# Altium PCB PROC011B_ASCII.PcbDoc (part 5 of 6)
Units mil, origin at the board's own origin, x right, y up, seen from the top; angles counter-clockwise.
Board outline 3304 x 2569 mil, 6 copper layers (TOP, L2-GND1, L3-GND/SIG, L4-GND/SIG, L5-GND2, BOTTOM), stack 55.77 mil thick; 376 components, 289 nets, 1284 pads, 1755 vias.
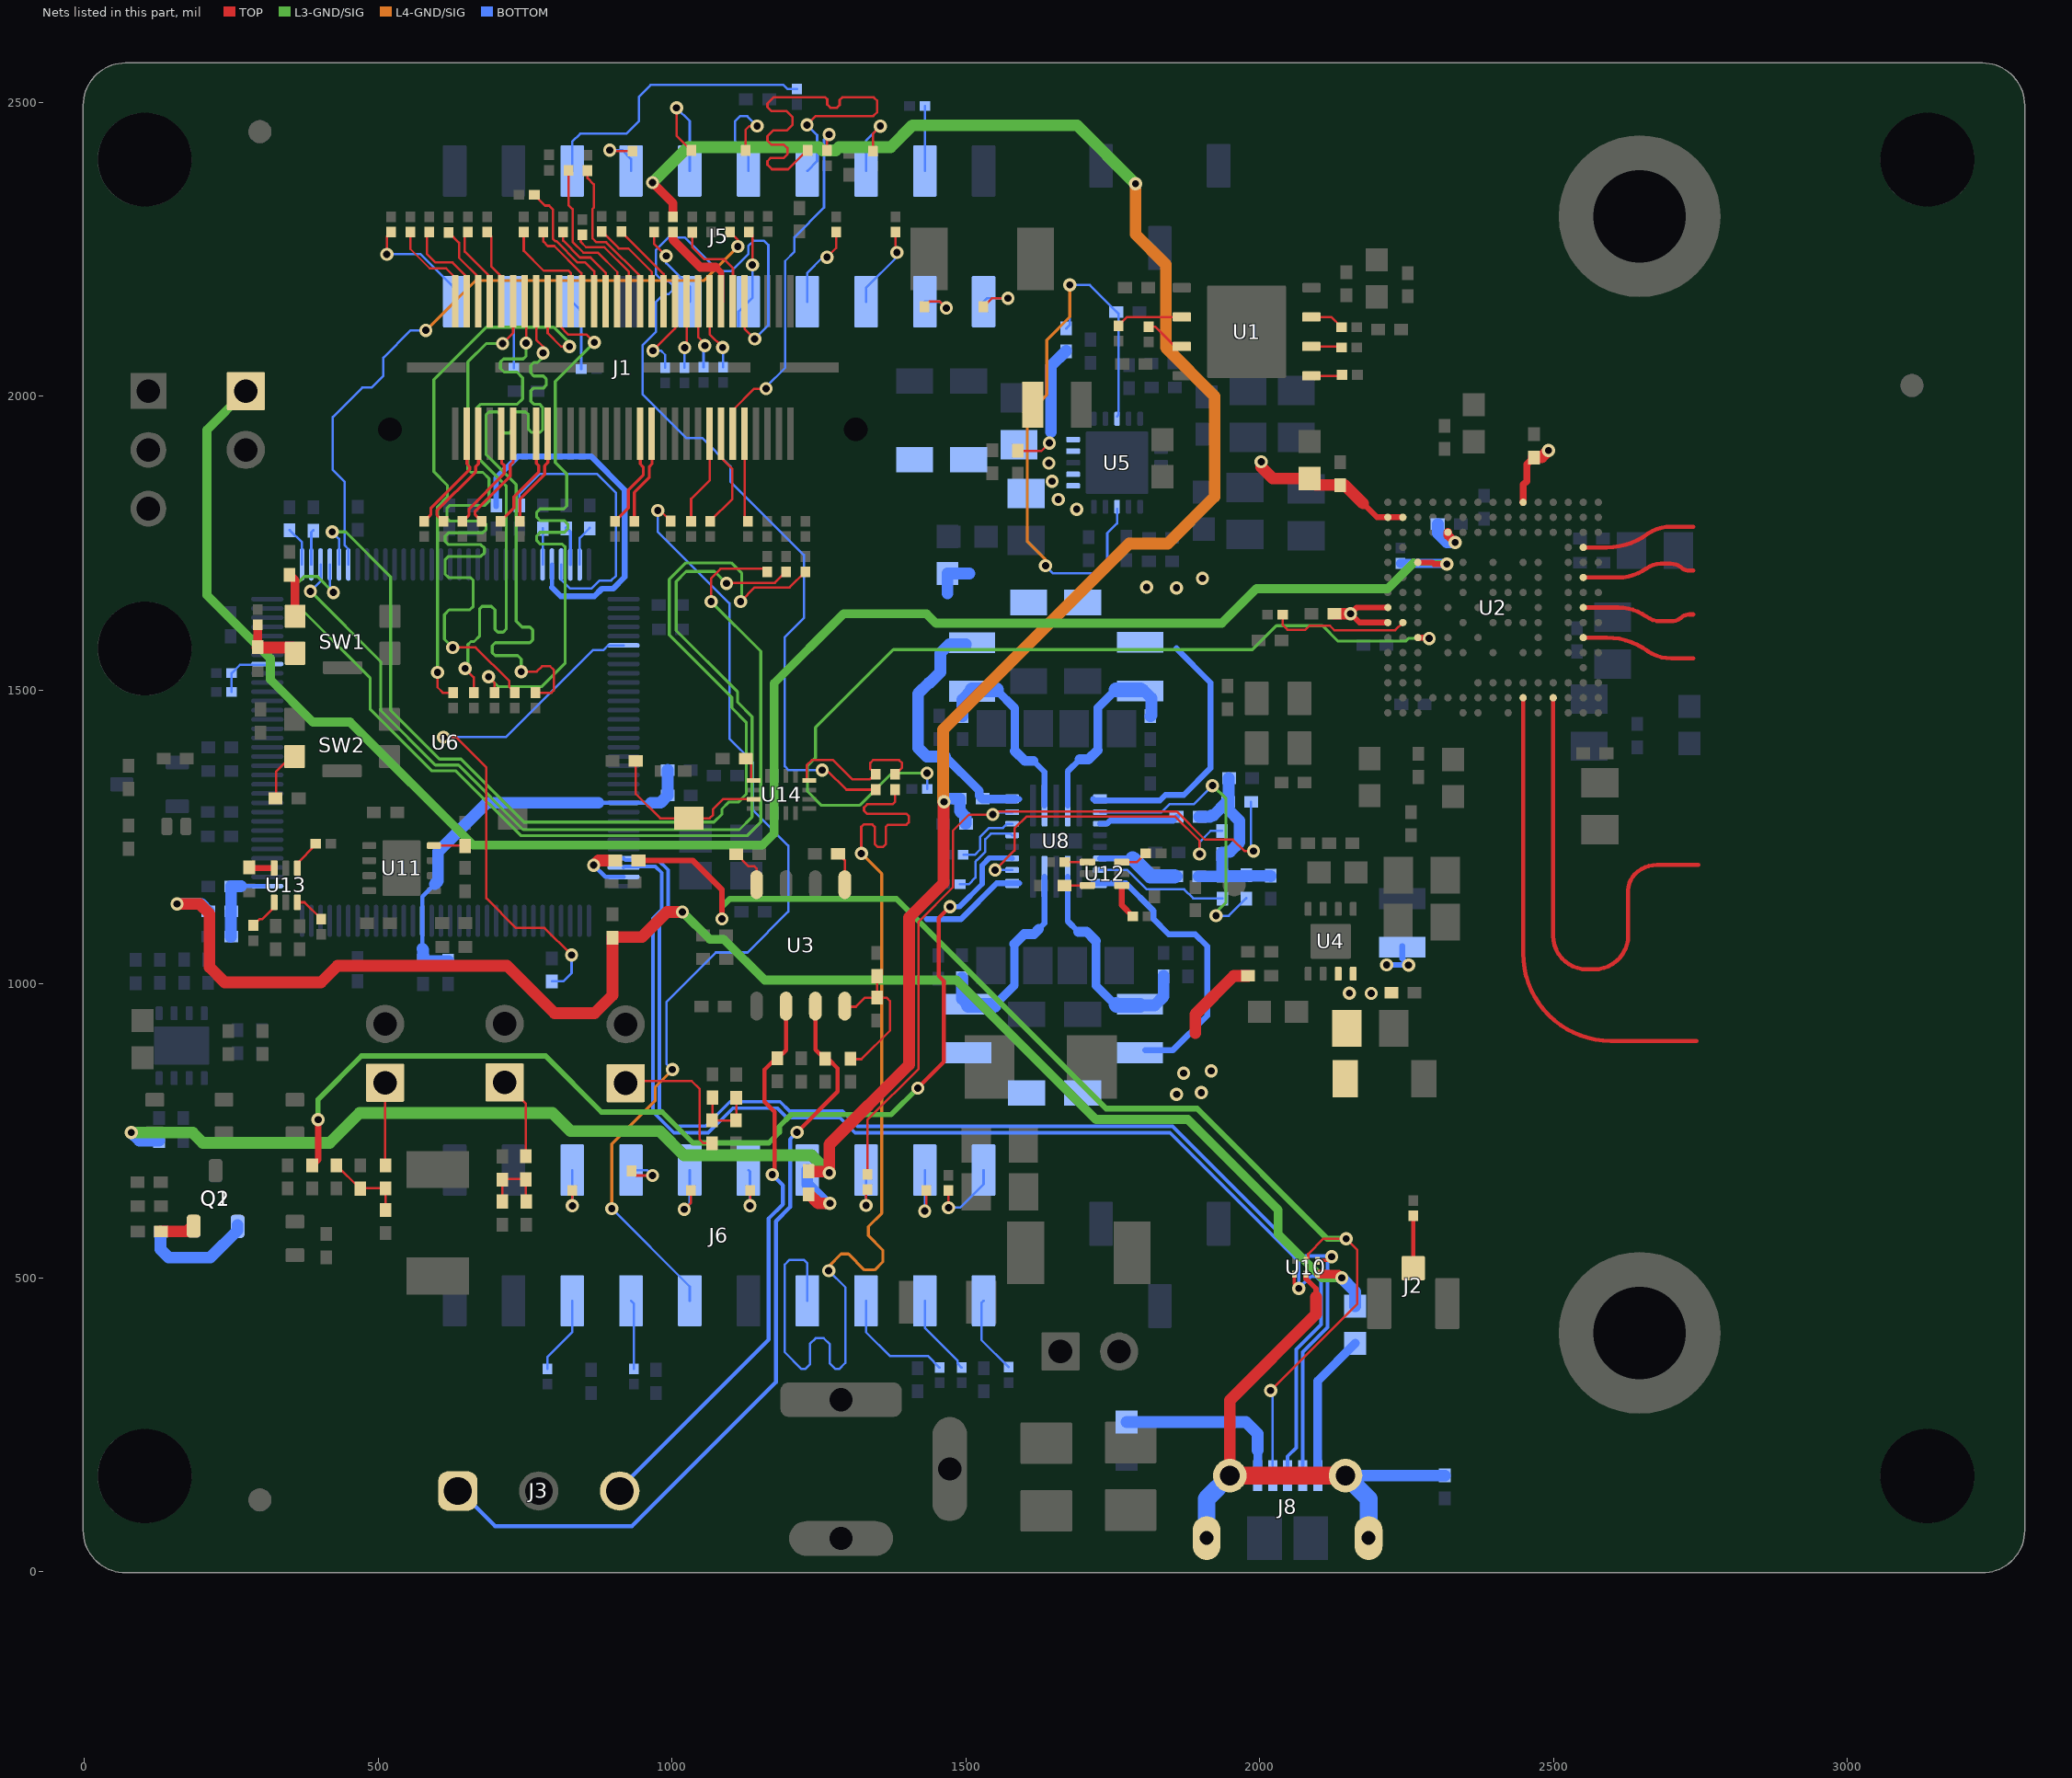
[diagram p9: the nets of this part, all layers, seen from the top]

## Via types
v1: diameter 22.4, hole 12.2, TOP to BOTTOM, tented both sides, 1046 vias
v2: diameter 15.74, hole 5.9, TOP to L2-GND1, tented both sides, 700 vias
v3: diameter 19.68, hole 7.87, TOP to BOTTOM, tented both sides, 9 vias

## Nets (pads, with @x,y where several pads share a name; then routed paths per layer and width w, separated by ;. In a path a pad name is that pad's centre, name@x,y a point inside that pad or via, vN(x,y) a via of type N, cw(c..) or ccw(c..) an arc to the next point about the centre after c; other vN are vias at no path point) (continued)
NetJ1_9: J1.9 R75.2 | length 1734.2
  TOP w4: J1.9@1123.49,2161.75 1123.49,2161.56 1123.49,2114.76 v1(1140.75,2097.5) ; v1(1255.52,1363.62) 1263.64,1363.62 1296.76,1330.51 R75.2@1346.75,1330.51
  BOTTOM w4: v1(1140.75,2097.5) 1164.05,2120.8 1164.05,2257.15 1156.46,2264.74 1139.39,2264.74 1129.85,2255.2 1129.85,2241.53 1100.94,2212.62 1079.22,2212.62 1022.14,2269.7 993.68,2269.7 972.45,2248.47 972.45,2207.63 984.38,2195.7 994.44,2195.7 1001.13,2189.01 1001.13,2180.38 994.43,2173.68 985.82,2173.68 972.45,2160.31 972.45,2109.37 949.76,2086.68 949.76,2003.46 1024.13,1929.09 1051.28,1929.09 1099.45,1880.92 1099.45,1854.8 1224.65,1729.6 1224.65,1622.75 1192.11,1590.21 1192.11,1370.14 1198.63,1363.62 v1(1255.52,1363.62)
NetJ1_10: J1.10 R64.1 | length 151
  TOP w4: J1.10@1123.49,1935.77 1123.49,1793.08 R64.1@1129.36,1787.21
NetJ1_11: J1.11 R28.2 | length 165.5
  TOP w4: R28.2@1034.25,2278.91 1034.25,2254 1054.75,2233.5 1088.16,2233.5 1103.81,2217.85 J1.11@1103.81,2161.75
NetJ1_12: J1.12 R7.1 | length 617.8
  TOP w4: J1.12@1103.4,1935.96 1103.4,1976.36 1139.88,2012.84 v1(1160.01,2012.84) ; J1.12@1103.81,1935.77 J1.12@1103.81,1935.96 ; R7.1@1264,2418.21 1264,2442.11 v1(1267.28,2445.39)
  BOTTOM w4: v1(1160.01,2012.84) 1160.01,2015.76 1192.62,2048.37 1192.62,2230.05 1208.45,2245.87 1208.45,2270.6 1258.75,2320.9 1258.75,2436.86 v1(1267.28,2445.39)
NetJ1_13: J1.13 R27.2 | length 167
  TOP w10: 1074.75,2219.5 1084.12,2210.13 J1.13@1084.12,2161.75
  TOP w15: R27.2@1001.55,2279.01 1001.55,2266.2 1048.25,2219.5 1074.75,2219.5
NetJ1_14: J1.14 R63.1 | length 172
  TOP w4: R63.1@1064.86,1787.21 1102.75,1825.1 1102.75,1875.89 1084.12,1894.52 J1.14@1084.12,1935.77
NetJ1_15: J1.15 R54.2 | length 121.7
  TOP w4: J1.15@1064.03,2161.56 1064.03,2105.22 v1(1086.25,2083) ; J1.15@1064.44,2161.56 J1.15@1064.44,2161.75
  BOTTOM w4: v1(1086.25,2083) 1086.75,2082.5 R54.2@1086.75,2049.49
NetJ1_16: J1.16 R62.1 | length 161.7
  TOP w4: R62.1@1032.6,1787.21 1032.6,1825.35 1064.44,1857.19 J1.16@1064.44,1935.77
NetJ1_17: J1.17 R55.2 | length 117.9
  TOP w4: J1.17@1044.75,2161.75 1044.75,2161.56 1044.75,2100.5 1055.87,2089.38 v1(1055.87,2086.09)
  BOTTOM w4: R55.2@1053.75,2049.29 1053.75,2075.5 1055.87,2077.62 v1(1055.87,2086.09)
NetJ1_19: J1.19 R56.2 | length 114.5
  TOP w4: v1(1021.75,2082.5) 1025.07,2085.82 1025.07,2161.56 J1.19@1025.07,2161.75
  BOTTOM w4: R56.2@1021.25,2048.79 1021.25,2082 v1(1021.75,2082.5)
NetJ1_21: J1.21 R57.2 | length 145
  TOP w4: v1(967.75,2077.5) 1005.38,2115.13 1005.38,2161.56 J1.21@1005.38,2161.75
  BOTTOM w4: v1(967.75,2077.5) 981.25,2077.5 988.35,2070.4 R57.2@988.35,2048.79
NetJ1_23: J1.23 R179.2 | length 148.1
  TOP w4: R179.2@913.75,2280.01 985.7,2208.06 J1.23@985.7,2161.75
NetJ1_25: J1.25 R180.2 | length 163.6
  TOP w4: R180.2@880.45,2280.21 881.04,2280.21 909.75,2251.5 925.75,2251.5 966.01,2211.24 J1.25@966.01,2161.75
NetJ1_26: J1.26 R59.1 | length 161.1
  TOP w5.2: R59.1@935.8,1787.21 935.8,1836.05 961.27,1861.52 961.27,1879.81 966.01,1884.55 J1.26@966.01,1935.77
NetJ1_27: J1.27 R181.2 | length 270.8
  TOP w4: R181.2@856.25,2383.81 856.25,2371 866.75,2360.5 866.75,2320.5 864.75,2318.5 864.75,2268.5 871.25,2262 887.85,2262 946.33,2203.52 J1.27@946.33,2161.75
NetJ1_28: J1.28 R58.1 | length 170.3
  TOP w5.2: R58.1@903.3,1787.21 925.6,1809.51 925.6,1840.28 951.07,1865.75 951.07,1879.81 946.33,1884.55 J1.28@946.33,1935.77
NetJ1_29: J1.29 R182.2 | length 166.1
  TOP w4: R182.2@847.75,2274.51 844.75,2271.51 844.75,2262.51 853.76,2253.5 884.75,2253.5 926.64,2211.61 J1.29@926.64,2161.75
NetJ1_31: J1.31 R183.2 | length 271.6
  TOP w4: R183.2@823.75,2384.21 823.75,2325.1 830.75,2318.1 830.75,2262.5 849.05,2244.2 874.05,2244.2 906.96,2211.29 J1.31@906.96,2161.75
NetJ1_33: J1.33 R184.2 | length 158.3
  TOP w4: R184.2@814.75,2279.51 814.75,2264.51 843.36,2235.9 861.35,2235.9 887.27,2209.98 J1.33@887.27,2161.75
NetJ1_35: J1.35 R185.2 | length 235.8
  TOP w4: R185.2@765.74,2342.5 783.94,2324.3 790.95,2324.3 797.35,2317.9 797.35,2267.9 801.75,2263.5 803.75,2263.5 839.65,2227.6 852.55,2227.6 867.59,2212.56 J1.35@867.59,2161.75
NetJ1_37: J1.37 R186.2 | length 151.9
  TOP w4: R186.2@781.05,2279.51 781.05,2263.2 788.75,2255.5 799.75,2255.5 845.75,2209.5 845.75,2163.9 847.79,2161.86 J1.37@847.9,2161.75
NetJ1_39: J1.39 R187.2 | length 176
  TOP w4: R187.2@747.75,2279.51 747.75,2247.5 781.75,2213.5 824.22,2213.5 828.22,2209.5 J1.39@828.22,2161.75
NetJ1_41: J1.41 R188.2 | length 1058.5
  TOP w4: v1(687.75,1522.6) 697.75,1512.6 R188.2@697.75,1495.59 ; J1.41@808.53,2161.75 808.53,2161.56 808.53,2119.92 823.95,2104.5 854.75,2104.5 v1(867.75,2091.5)
  L3-GND/SIG w5: v1(687.75,1522.6) 704.77,1505.58 777.83,1505.58 818.25,1546 818.25,1743.34 813.25,1748.34 775.61,1748.34 769.75,1754.2 769.75,1762.48 775.61,1768.34 816.89,1768.34 822.75,1774.2 822.75,1782.48 816.89,1788.34 775.61,1788.34 769.75,1794.2 769.75,1802.48 775.61,1808.34 815.85,1808.34 820.85,1813.34 820.85,1867.9 801.35,1887.4 801.35,2025.1 v1(867.75,2091.5)
NetJ1_43: J1.43 R189.2 | length 956.7
  TOP w4: v1(601.05,1530.2) 601.05,1504.6 610.06,1495.59 R189.2@627.75,1495.59 ; J1.43@788.44,2161.56 788.44,2107.29 811.23,2084.5 v1(825.75,2084.5) ; J1.43@788.85,2161.56 J1.43@788.85,2161.75
  L3-GND/SIG w5: v1(601.05,1530.2) 601.05,1811.8 617.75,1828.5 617.75,1848.5 594.75,1871.5 594.75,2028 684.25,2117.5 798.75,2117.5 825.75,2090.5 v1(825.75,2084.5)
NetJ1_44: J1.44 R53.1 | length 168.4
  TOP w5.2: R53.1@741,1787.21 741,1824.74 783.25,1866.99 783.25,1881.49 788.85,1887.09 J1.44@788.85,1935.77
NetJ1_45: J1.45 R190.2 | length 1191.9
  TOP w4: v1(743.45,1531.4) 769.65,1531.4 778.75,1540.5 792.75,1540.5 798.75,1534.5 798.75,1499.59 794.75,1495.59 R190.2@767.75,1495.59 ; J1.45@769.16,2161.75 769.16,2161.56 769.16,2096.09 780.75,2084.5 v1(780.75,2073.5) v1@780.75,2072.5
  L3-GND/SIG w5: v1(743.45,1531.4) 743.45,1552.7 737.55,1558.6 699.29,1558.6 694.29,1563.6 694.29,1575.5 699.29,1580.5 758.15,1580.5 763.15,1585.5 763.15,1602.2 758.15,1607.2 744.75,1607.2 734.75,1617.2 734.75,1849.5 683.75,1900.5 683.75,1968.5 688.75,1973.5 703.18,1973.5 709.04,1967.64 709.04,1943.36 714.9,1937.5 723.18,1937.5 729.04,1943.36 729.04,1967.64 734.9,1973.5 750.75,1973.5 755.75,1968.5 755.75,1943.5 760.75,1938.5 775.75,1938.5 779.75,1942.5 779.75,1981.5 774.75,1986.5 764.75,1986.5 759.75,1991.5 759.75,2009.5 763.75,2013.5 780.95,2013.5 785.95,2018.5 785.95,2029.5 780.95,2034.5 764.87,2034.5 759.87,2039.5 759.87,2052.5 764.87,2057.5 771.75,2057.5 780.75,2066.5 v1@780.75,2072.5
NetJ1_46: J1.46 R52.1 | length 176.9
  TOP w5.2: R52.1@708.5,1787.21 730.8,1809.51 730.8,1828.97 773.05,1871.22 773.05,1881.7 769.16,1885.59 J1.46@769.16,1935.77
NetJ1_47: J1.47 R191.2 | length 963.5
  TOP w4: v1(647.85,1536.7) 662.75,1521.8 R191.2@662.75,1495.59 ; J1.47@749.48,2161.75 751.75,2159.48 v1(751.75,2090.5)
  L3-GND/SIG w5: v1(647.85,1536.7) 652.75,1541.6 652.75,1577.5 657.75,1582.5 663.16,1582.5 672.75,1592.09 672.75,1638.5 676.75,1642.5 692.75,1642.5 698.75,1636.5 698.75,1603.5 703.75,1598.5 712.75,1598.5 717.85,1603.6 717.85,1847.4 667.75,1897.5 667.75,1979.51 674.74,1986.5 736.75,1986.5 745.75,1995.5 745.75,2031.5 736.25,2041 714.25,2041 708.29,2046.96 708.29,2058.5 713.29,2063.5 746.75,2063.5 751.75,2068.5 v1(751.75,2090.5)
NetJ1_49: J1.49 R192.2 | length 1204.6
  TOP w4: v1(626.75,1572.4) 665.85,1572.4 723.15,1515.1 723.15,1505.19 R192.2@732.75,1495.59 ; v1(711.75,2089.5) 729.79,2107.54 729.79,2161.56 J1.49@729.79,2161.75
  L3-GND/SIG w5: v1(626.75,1572.4) 612.75,1586.4 612.75,1628.5 620.75,1636.5 655.75,1636.5 661.75,1642.5 661.75,1686.5 656.75,1691.5 619.75,1691.5 613.75,1697.5 613.75,1721.57 619.61,1727.43 674.89,1727.43 680.75,1733.29 680.75,1741.57 674.89,1747.43 619.61,1747.43 613.75,1753.29 613.75,1761.57 619.61,1767.43 677.89,1767.43 683.75,1773.29 683.75,1781.57 677.89,1787.43 621.95,1787.43 616.95,1792.43 616.95,1809.3 621.95,1814.3 681.55,1814.3 688.75,1821.5 688.75,1859.8 678.05,1870.5 657.75,1870.5 652.75,1875.5 652.75,2058.35 683.9,2089.5 v1(711.75,2089.5)
NetJ1_50: J1.50 R51.1 | length 180.1
  TOP w5.2: R51.1@676,1787.21 664.85,1798.36 664.85,1804.11 724.75,1864.01 724.75,1883.01 729.79,1888.05 J1.50@729.79,1935.77
NetJ1_51: J1.51 R23.2 | length 127.7
  TOP w4: R23.2@685.36,2279.23 692.75,2271.84 692.75,2220.5 710.11,2203.14 J1.51@710.11,2161.75
NetJ1_52: J1.52 R50.1 | length 179.8
  TOP w5.2: R50.1@643.5,1787.21 654.65,1798.36 654.65,1808.34 714.55,1868.24 714.55,1882.21 710.11,1886.65 J1.52@710.11,1935.77
NetJ1_53: J1.53 R22.2 | length 137.5
  TOP w4: R22.2@652.86,2279.23 647.45,2273.82 647.45,2245.81 690.42,2202.84 J1.53@690.42,2161.75
NetJ1_55: J1.55 R33.2 | length 138
  TOP w4: R33.2@620.14,2278.79 637.75,2261.18 637.75,2235.5 670.74,2202.51 J1.55@670.74,2161.75
NetJ1_56: J1.56 R49.1 | length 182.6
  TOP w5.2: R49.1@611,1787.21 599.78,1798.43 599.78,1805.03 665.95,1871.2 665.95,1880.38 670.74,1885.17 J1.56@670.74,1935.77
NetJ1_57: J1.57 R21.2 | length 164.6
  TOP w4: R21.2@587.1,2279.23 582.75,2274.88 582.75,2242.51 597.76,2227.5 626.75,2227.5 651.05,2203.2 J1.57@651.05,2161.75
NetJ1_58: J1.58 R48.1 | length 182.6
  TOP w5.2: R48.1@578.36,1787.21 589.58,1798.43 589.58,1809.26 655.75,1875.43 655.75,1879.85 651.05,1884.55 J1.58@651.05,1935.77
NetJ1_59: J1.59 R20.2 | length 165.6
  TOP w4: R20.2@554.86,2279.23 554.86,2250.39 587.75,2217.5 615.76,2217.5 631.37,2201.89 J1.59@631.37,2161.75
NetJ2_1: J2.1 R111.2 | length 89.5
  TOP w7.08: J2.1@2261.46,516.26 2261.61,516.41 R111.2@2261.61,605.68
NetJ3_1: J3.1 R85.2 U3.7 | length 1370.5
  TOP w7: v1(1212.75,747.5) 1281.85,816.6 1281.85,856.3 1265.95,872.2 1260.75,872.2 1259.75,872.2 1244.06,887.89 U3.7@1244.06,961.15
  BOTTOM w7: J3.1@635.55,141.16 637.52,139.19 699.18,77.53 931.78,77.53 1176.75,322.5 1176.75,596.1 1200.95,620.3 1200.95,735.7 v1(1212.75,747.5)
NetJ3_3: J3.3 R87.1 U3.6 | length 968.7
  TOP w7: v1(1170.75,675.5) 1174.75,679.5 1174.75,782.3 1157.25,799.8 1157.25,854 1176.05,872.8 1179.45,872.8 1179.84,873.19 1194.06,887.41 U3.6@1194.06,961.15
  BOTTOM w7: J3.3@911.14,141.16 1164.75,394.77 1164.75,601.1 1188.95,625.3 1188.95,657.3 v1(1170.75,675.5)
NetJ5_1: J5.1 R19.2 | length 203
  TOP w4: v1(514.75,2241.5) 514.75,2271.98 R19.2@522,2279.23
  BOTTOM w4: v1(514.75,2241.5) 572.25,2241.5 630.25,2183.5 J5.1@630.25,2160.78
NetJ5_3: J5.3 R24.2 | length 112.9
  BOTTOM w4: J5.3@730.25,2160.78 730.86,2160.17 R24.2@730.86,2048.1
NetJ5_5: J5.5 R25.2 | length 120.8
  BOTTOM w4: J5.5@830.25,2160.78 845.56,2145.47 R25.2@845.56,2046.3
NetJ5_6: J5.6 R1.1 | length 499.1
  BOTTOM w4: J5.6@830.25,2383.22 830.25,2432.9 843.85,2446.5 922.35,2446.5 943.45,2467.6 943.45,2509.1 963.75,2529.4 1189.81,2529.4 1196.72,2522.49 R1.1@1212.55,2522.49
NetJ5_8: J5.8 R9.1 | length 102
  TOP w4: v1(893.95,2418.7) 895.44,2417.21 R9.1@932.5,2417.21
  BOTTOM w4: v1(893.95,2418.7) 914.95,2418.7 930.25,2403.4 J5.8@930.25,2383.22
NetJ5_9: J5.9 R26.2 | length 143.5
  TOP w4: R26.2@969.45,2279.11 969.45,2259.2 v1(990.15,2238.5)
  BOTTOM w4: v1(990.15,2238.5) 990.15,2226.45 1030.25,2186.35 J5.9@1030.25,2160.78
NetJ5_10: J5.10 R2.1 | length 199.3
  TOP w4: v1(1007.75,2490.5) 1007.75,2443.26 R2.1@1032.8,2418.21
  BOTTOM w4: v1(1007.75,2490.5) 1030.25,2468 J5.10@1030.25,2383.22
NetJ5_11: J5.11 R18.2 | length 172.7
  TOP w4: R18.2@1130.96,2279.58 1131.17,2279.58 1136.85,2273.9 v1(1136.85,2223.5)
  BOTTOM w4: J5.11@1113.17,2119.29 1113.17,2143.7 J5.11@1130.25,2160.78 1136.85,2167.38 v1(1136.85,2223.5)
NetJ5_12: J5.12 R4.1 | length 199.5
  TOP w4: R4.1@1125.3,2418.21 1125.3,2453.37 1131.58,2459.65 v1(1144.9,2459.65)
  BOTTOM w4: J5.12@1130.25,2383.22 1130.25,2410.9 1107.4,2433.75 1107.4,2468.08 1115.64,2476.32 1128.23,2476.32 v1(1144.9,2459.65)
NetJ5_13: J5.13 R31.2 | length 142.9
  TOP w4: v1(1263.75,2236.5) 1279.5,2252.25 R31.2@1279.5,2279.23
  BOTTOM w4: J5.13@1230.25,2160.78 1230.25,2209.97 1256.78,2236.5 v1(1263.75,2236.5)
NetJ5_14: J5.14 R6.1 | length 765.3
  TOP w4: v1(1229.75,2461.5) 1244.95,2476.7 1342.73,2476.7 1349.14,2483.11 1349.14,2502.84 1343.4,2508.58 1289.89,2508.58 1285.34,2504.03 1285.34,2495.57 1280.64,2490.87 1269.58,2490.87 1264.22,2496.23 1264.22,2505.35 1260.99,2508.58 1173.01,2508.58 1162.45,2498.02 1162.45,2491.95 1169.58,2484.82 1195.05,2484.82 1205.35,2474.52 1205.35,2462.24 1195.06,2451.95 1172.03,2451.95 1162.45,2442.37 1162.45,2434.73 1169.38,2427.8 1190.59,2427.8 1196.18,2422.21 1196.18,2411.25 1190.37,2405.44 1168.04,2405.44 1162.45,2399.85 1162.45,2393.77 1170.05,2386.17 1197.52,2386.17 1229.56,2418.21 R6.1@1230.8,2418.21
  BOTTOM w4: v1(1229.75,2461.5) 1247.02,2444.23 1247.02,2399.99 J5.14@1230.25,2383.22
NetJ5_15: J5.15 R32.2 | length 141.2
  TOP w4: R32.2@1380.3,2279.23 1380.75,2278.78 1380.75,2246.5 v1(1382.75,2244.5)
  BOTTOM w4: J5.15@1330.25,2160.78 1330.25,2184 1382.75,2236.5 v1(1382.75,2244.5)
NetJ5_16: J5.16 R10.1 | length 134
  TOP w4: R10.1@1342,2417.21 1342,2446.75 v1(1354.75,2459.5)
  BOTTOM w4: J5.16@1330.25,2383.22 1330.25,2435 v1(1354.75,2459.5)
NetJ5_17: J5.17 R35.2 | length 86.4
  TOP w4: R35.2@1429.5,2152.21 1438.29,2161 1455.75,2161 v1(1466.75,2150)
  BOTTOM w4: J5.17@1430.25,2160.78 1455.97,2160.78 v1(1466.75,2150)
NetJ5_18: J5.18 R8.1 | length 110.3
  BOTTOM w4: J5.18@1430.25,2383.22 R8.1@1430.25,2493.5
NetJ5_19: J5.19 R36.2 | length 91.5
  TOP w4: R36.2@1530,2152.21 1544.29,2166.5 v1(1571.75,2166.5)
  BOTTOM w4: J5.19@1530.25,2160.78 1535.97,2166.5 v1(1571.75,2166.5)
NetJ6_5: J6.5 R169.2 | length 133.6
  BOTTOM w4: R169.2@787.88,344.77 787.88,364.83 830.25,407.2 J6.5@830.25,460.78
NetJ6_6: J6.6 R104.1 | length 87.1
  TOP w4: v1(830.5,622.5) R104.1@830.5,648.79
  BOTTOM w4: J6.6@830.25,683.22 830.25,622.75 v1(830.5,622.5)
NetJ6_7: J6.7 R166.2 | length 118.2
  BOTTOM w4: J6.7@930.25,460.78 935.5,455.53 R166.2@935.5,344.77
NetJ6_8: J6.8 R94.1 | length 79.3
  TOP w4: R94.1@931,681.79 938.79,674 v1(966.75,674)
  BOTTOM w4: J6.8@930.25,683.22 957.53,683.22 v1(966.75,674)
NetJ6_9: J6.9 R165.2 | length 1685.5
  TOP w4: v1(975.75,1805.5) 979.74,1805.5 R165.2@997.75,1787.49
  L4-GND/SIG w5: v1(897.75,617.5) 897.75,727.85 971.75,801.85 971.75,825.08 1000.65,853.98 v1(1000.65,854.2)
  BOTTOM w4: v1(897.75,617.5) 1030.25,485 J6.9@1030.25,460.78 ; v1(975.75,1805.5) 975.75,1769.5 1097.75,1647.5 1097.75,1417.25 1137.92,1377.08 1137.92,1295.52 1198.05,1235.39 1198.05,1122.8 1128.75,1053.5 1074.75,1053.5 990.55,969.3 990.55,864.3 v1(1000.65,854.2)
NetJ6_10: J6.10 R105.1 | length 108
  TOP w4: v1(1020.75,616.4) 1032.5,628.15 R105.1@1032.5,648.79
  BOTTOM w4: v1(1020.75,616.4) 1030.25,625.9 J6.10@1030.25,683.22
NetJ6_12: J6.12 R106.1 | length 88.1
  TOP w4: v1(1132.75,622.5) 1133,622.75 R106.1@1133,648.79
  BOTTOM w4: J6.12@1130.25,683.22 1132.75,680.72 v1(1132.75,622.5)
NetJ6_13: J6.13 R76.2 | length 1850.2
  TOP w4: v1(1322.35,1221.9) 1322.15,1222.1 1322.15,1267.4 1326.15,1271.4 1340.95,1271.4 1344.95,1267.4 1344.95,1238.4 1350.35,1233 1358.85,1233 1364.25,1238.4 1364.25,1267.5 1367.75,1271 1399.05,1271 1403.05,1275 1403.05,1285.62 1399.04,1289.63 1331.84,1289.63 1326.85,1294.62 1326.85,1300.18 1332.3,1305.63 1375.06,1305.63 1379.75,1310.32 R76.2@1379.75,1330.51
  L4-GND/SIG w5: v1(1266.75,512) 1266.75,519.5 1287.73,540.48 1300.29,540.48 1327.37,513.4 1345.04,513.4 1358.85,527.21 1358.85,547.11 1334.33,571.62 1334.33,587.08 1356.85,609.6 1356.85,1187.4 v1(1322.35,1221.9)
  BOTTOM w4: J6.13@1230.25,460.78 1230.25,524.45 1224.09,530.61 1200.24,530.61 1191.85,522.22 1191.85,373.64 1220.69,344.8 1226.9,344.8 1234.66,352.56 1234.66,387.23 1244.68,397.25 1258.36,397.25 1268.56,387.05 1268.56,354.24 1278,344.8 1284.62,344.8 1295.11,355.29 1295.11,483.64 v1(1266.75,512)
NetJ6_14: J6.14 R107.1 | length 119.2
  TOP w20: R107.1@1232.5,642.88 1232.89,642.49 1248.88,626.5 v1(1268.75,626.5)
  BOTTOM w20: J6.14@1230.25,683.22 1230.25,659 1262.75,626.5 v1(1268.75,626.5)
NetJ6_15: J6.15 R164.2 | length 203.5
  BOTTOM w4: J6.15@1330.25,460.78 1330.25,407.5 1371.25,366.5 1436.21,366.5 R164.2@1455.5,347.21
NetJ6_16: J6.16 R102.1 | length 88.1
  TOP w4: v1(1330.25,623) 1330.25,647.04 R102.1@1333,649.79
  BOTTOM w4: v1(1330.25,623) J6.16@1330.25,683.22
NetJ6_17: J6.17 R163.2 | length 139.6
  BOTTOM w4: J6.17@1430.25,460.78 1430.25,414.73 1485.75,359.23 1485.75,354.46 R163.2@1493,347.21
NetJ6_18: J6.18 R108.1 | length 106
  TOP w4: v1(1430.25,613.5) 1433.1,616.35 R108.1@1433.1,648.59
  BOTTOM w4: v1(1430.25,613.5) J6.18@1430.25,683.22
NetJ6_19: J6.19 R162.2 | length 133.6
  BOTTOM w4: J6.19@1530.25,460.78 1526.75,457.28 1526.75,394.02 R162.2@1573,347.77
NetJ6_20: J6.20 R109.1 | length 129.5
  TOP w4: v1(1470.6,619.3) R109.1@1470.6,648.59
  BOTTOM w4: v1(1470.6,619.3) 1490.36,619.3 1530.25,659.19 J6.20@1530.25,683.22
NetJ8_1: J8.1 R161.1 | length 251.7
  BOTTOM w10: J8.1@2098.75,163.56 J8.1@2098.93,163.38
  BOTTOM w15: J8.1@2098.75,163.56 2098.75,324.5 R161.1@2162.75,388.5
NetJ8_5: J8.5 R175.2 | length 302.5
  BOTTOM w15: J8.5@1996.57,163.38 1996.75,163.56 1996.75,206.5
  BOTTOM w20: R175.2@1773.75,254.5 1976.75,254.5 1996.75,234.5 1996.75,206.5
NetJ8_6: J8.6 J8.9 J8.10 J8.11 R174.2 U10.5 | length 1021.8
  TOP w9: U10.5@2078.75,506.19 2078.75,498.49 2095.96,481.28
  TOP w10: 2095.96,467.21 2095.96,481.28
  TOP w20: J8.10@1949.32,163.38 1949.32,291.57 2095.96,438.21 2095.96,467.21
  TOP w30: J8.10@1949.32,163.38 J8.11@2146.18,163.38
  BOTTOM w20: J8.11@2146.18,163.38 2315.06,163.38 R174.2@2315.15,163.29
  BOTTOM w30: J8.9@1909.95,57.08 1909.95,124.01 J8.10@1949.32,163.38 ; J8.11@2146.18,163.38 2185.55,124.01 J8.6@2185.55,57.08
NetP2_1: P2.1 R95.2 | length 141.4
  TOP w4: P2.1@715.19,832.25 751.57,795.87 R95.2@751.57,706.74 R95.2@751.57,705.95
NetP3_1: P3.1 R99.2 | length 141.6
  TOP w4: P3.1@511.75,831.92 511.75,691.34 511.75,691.17 511.98,690.94 R99.2@512.37,690.55
NetP4_1: P4.1 R92.2 | length 242.7
  TOP w4: P4.1@921.19,831.25 924.64,834.7 1033.75,834.7 1046.75,821.7 1046.75,735.51 1052.81,729.45 R92.2@1068.37,729.45
NetQ1_1: Q1.1 R116.2 | length 61.1
  TOP w20: R116.2@129.43,578.83 R116.2@130.22,578.83 174.79,578.83 184.95,588.99 Q1.1@185.93,589.97
NetQ2_1: Q2.1 R160.2 | length 195
  BOTTOM w20: R160.2@129.35,578.41 129.35,548.4 143.5,534.25 214,534.25 260.77,581.02 Q2.1@260.77,587.43 Q2.1@260.77,589.39
NetR3_1: R3.1 U12.3 | length 40.2
  TOP w4: R3.1@1666.95,1167.6 1667.06,1167.71 1667.74,1167.71 U12.3@1707.12,1167.71
NetR5_2: R5.2 U12.1 | length 38.5
  TOP w4: R5.2@1668.64,1207 1668.73,1207.09 U12.1@1707.12,1207.09
NetR11_2: R11.2 U3.1 | length 57.3
  TOP w4: R11.2@1282.64,1221.42 1294.06,1210 U3.1@1294.06,1168.83
NetR12_2: R12.2 U3.4 | length 72.4
  TOP w4: R12.2@1109.22,1220.7 1109.67,1220.7 1130.38,1199.99 1140.28,1199.99 1144.06,1196.21 U3.4@1144.06,1168.83
NetR39_2: R39.2 U1.2 | length 112.1
  TOP w4: R39.2@1759.65,2119.99 1774.34,2134.68 U1.2@1865.68,2134.68
NetR40_1: R40.1 U1.7 | length 56.5
  TOP w4: U1.7@2090.08,2134.68 2122.11,2134.68 R40.1@2139.44,2117.35
NetR42_2: R42.2 U1.3 | length 68.4
  TOP w4: R42.2@1811.25,2118.29 1822.27,2118.29 1855.88,2084.68 U1.3@1865.68,2084.68
NetR44_1: R44.1 U1.6 | length 50.1
  TOP w4: U1.6@2090.08,2084.68 2137.61,2084.68 R44.1@2139.44,2082.85
NetR45_1: R45.1 U1.5 | length 51.1
  TOP w4: U1.5@2090.08,2034.68 2138.77,2034.68 R45.1@2140.44,2036.35
NetR68_1: R68.1 SW1.4 | length 69.3
  TOP w15: R68.1@348.79,1696.75 349.18,1696.36 358.69,1686.85 SW1.4@358.69,1631.52
NetR72_1: R72.1 R73.2 SW1.2 | length 104.1
  TOP w15: R73.2@294.8,1572.32 295.19,1572.71 295.25,1572.77 295.25,1573.11 R72.1@295.25,1610.76
  TOP w20: R73.2@294.8,1572.32 354.89,1572.32 SW1.2@358.69,1568.52
NetR79_2: R79.2 SW2.2 | length 90.4
  TOP w4: R79.2@326.1,1315.64 326.1,1361.26 354.79,1389.95 SW2.2@357.74,1392.9
NetR86_1: R86.1 R177.2 R178.1 U3.8 | length 261.2
  TOP w4: U3.8@1294.06,961.15 1312.86,961.15 1327.81,976.1 R86.1@1349.05,976.1 ; R178.1@1303.55,872 1322.45,872 1371.05,920.6 1371.05,970.9 1365.85,976.1 R86.1@1349.05,976.1 ; R177.2@1349.25,1013.95 R177.2@1349.25,1013.16 1349.25,994.5 1349.05,994.3 R86.1@1349.05,976.89 R86.1@1349.05,976.1
NetR88_2: R88.2 R89.2 R92.1 R93.1 | length 120.8
  TOP w4: R88.2@1068.87,807.45 R88.2@1068.87,806.66 1068.87,768.04 1068.87,767.75 1068.76,767.64 1068.37,767.25 1108.57,767.25 1108.96,767.64 R93.1@1109.33,768.01 ; R93.1@1109.33,768.04 R89.2@1109.33,806.36 R89.2@1109.33,807.15
NetR95_1: R95.1 R96.2 R112.1 R113.2 | length 118.5
  TOP w4: R113.2@711.67,628.95 711.53,629.09 711.53,629.74 R96.2@711.53,667.06 711.53,667.85 751.27,667.85 751.57,668.15 R95.1@751.57,667.36 751.57,629.74 751.57,629.45 751.68,629.34 R112.1@752.07,628.95
NetR98_2: R98.2 R99.1 R101.1 R114.2 | length 137.9
  TOP w4: R98.2@428.57,690.55 430.19,690.55 468.29,652.45 469.73,652.45 470.03,652.75 512.37,652.75 R99.1@512.37,651.96 512.37,615.34 512.37,614.65 R114.2@512.27,614.55
NetR123_1: R123.1 U6.63 | length 69.2
  BOTTOM w4: U6.63@842.89,1713.69 842.89,1758.61 859.64,1775.36 R123.1@860.03,1775.75
NetR124_1: R124.1 U6.61 | length 487.2
  BOTTOM w4: R124.1@740.47,1813.25 R124.1@740.47,1814.04 740.47,1833.72 774.25,1867.5 872.75,1867.5 904.75,1835.5 904.75,1694.5 896.75,1686.5 876.75,1686.5 863.25,1673 826.25,1673 811.75,1687.5 811.75,1713.33 U6.61@811.39,1713.69
NetR125_2: R125.2 U6.59 | length 61.9
  BOTTOM w4: U6.59@779.89,1713.69 779.89,1774.66 779.89,1775.07 R125.2@780.27,1775.45
NetR126_1: R126.1 U6.62 | length 64.8
  BOTTOM w6: R126.1@820.43,1775.75 820.82,1775.36 827.14,1769.04 U6.62@827.14,1713.69
NetR127_1: R127.1 U6.60 | length 636.2
  BOTTOM w7: 795.64,1674.61 U6.60@795.64,1713.69
  BOTTOM w10: R127.1@700.87,1813.25 R127.1@700.87,1814.04 700.87,1860.61 737.76,1897.5 862.75,1897.5 919.75,1840.5 919.75,1692.5 899.75,1672.5 880.75,1672.5 867.75,1659.5 810.75,1659.5 795.64,1674.61
NetR128_2: R128.2 U6.33 | length 67.5
  BOTTOM w4: R128.2@349.25,1772.45 349.64,1772.06 370.45,1751.25 U6.33@370.45,1713.69
NetR129_2: R129.2 U6.34 | length 59.9
  BOTTOM w4: U6.34@386.19,1713.69 386.19,1768.54 389.36,1771.71 R129.2@389.75,1772.1
NetR135_2: R135.2 R136.2 U6.25 | length 99.3
  BOTTOM w4: R136.2@250.52,1496.79 R135.2@250.52,1528.69 264.83,1543 309.99,1543 U6.25@311.39,1544.4
NetR143_1: R143.1 U8.16 | length 135.7
  BOTTOM w10: U8.16@1728.55,1272.53 1740.28,1272.53 1745.75,1278 1853.05,1278 1858.96,1283.91 R143.1@1859.35,1284.3
NetR144_1: R144.1 U8.6 | length 117.6
  BOTTOM w4: R144.1@1496.04,1219.6 1515.35,1219.6 1524.15,1228.4 1524.15,1250.2 1539.45,1265.5 1563.25,1265.5 1570.28,1272.53 U8.6@1578.95,1272.53
NetR146_2: R146.2 U8.5 | length 153.9
  BOTTOM w4: R146.2@1490.34,1169.5 1504.94,1169.5 1516.25,1180.81 1516.25,1208 1518.85,1210.6 1519.15,1210.6 1533.15,1224.6 1533.15,1246.1 1542.55,1255.5 1576.29,1255.5 U8.5@1578.95,1252.84
NetR147_1: R147.1 U8.19 | length 142.9
  BOTTOM w10: U8.19@1728.55,1213.47 1783.98,1213.47
  BOTTOM w20: R147.1@1854.75,1183 R147.1@1858.07,1183 R147.1@1858.85,1183
  BOTTOM w25: 1783.98,1213.47 1814.45,1183 R147.1@1854.75,1183
NetR152_1: R152.1 U6.95 | length 99.3
  TOP w20: v1(866.75,1202) 874.75,1210 R152.1@903.61,1210
  BOTTOM w7: v1(866.75,1202) 886.56,1182.19 U6.95@917.69,1182.19
NetR155_1: R155.1 U6.70 | length 943.3
  TOP w4: v1(611.15,1419.8) 632.49,1419.8 684.01,1368.28 684.01,1145.62 734.46,1095.17 783.29,1095.17 v1(829.15,1049.3)
  BOTTOM w4: v1(611.15,1419.8) 717.25,1419.8 865.25,1567.8 883.24,1567.8 891.33,1575.89 U6.70@917.69,1575.89 ; R155.1@795.53,1004.75 815.49,1004.75 829.15,1018.41 v1(829.15,1049.3)
NetR167_2: R167.2 U12.4 | length 60.5
  TOP w10: U12.4@1765.38,1167.71 1765.38,1134.08 R167.2@1784.36,1115.1
NetR168_1: R168.1 U12.6 | length 47.3
  TOP w4: U12.6@1765.38,1207.09 1791.05,1207.09 R168.1@1806.36,1222.4
NetR194_2: R194.2 U11.8 | length 48.9
  TOP w4: U11.8@598.71,1235.39 R194.2@647.65,1235.39
NetR197_1: R197.1 U13.3 | length 42.8
  TOP w10: R197.1@280.55,1197.8 281.32,1197.03 U13.3@323.07,1197.03
NetR198_2: R198.2 U13.1 | length 54.1
  TOP w4: U13.1@362.44,1197.03 362.44,1205.58 393.36,1236.5 R198.2@393.36,1238.3
NetR199_1: R199.1 U13.6 | length 52.4
  TOP w4: U13.6@362.44,1138.77 374.57,1138.77 R199.1@403.05,1110.29
NetR201_1: R201.1 U13.4 | length 56.6
  TOP w4: R201.1@287.65,1099.69 297.96,1110 302.84,1110 323.06,1130.22 U13.4@323.07,1138.77
NetR206_1: R206.1 S2.2 U14.15 | length 295.6
  TOP w4: R206.1@938.29,1379.34 938.29,1323.5 979.94,1281.85 S2.2@1028.93,1281.85 1064.17,1281.85 1070,1287.68 1070,1297.5 1087.16,1314.66 1137.1,1314.66 1139.03,1312.73 U14.15@1139.03,1314.34
NetR208_1: R208.1 U14.13 | length 43.5
  TOP w4: R208.1@1125.5,1383.62 1134.79,1374.34 1134.79,1345.83 U14.13@1134.79,1344.01
NetR210_2: R210.2 U2.G14 | length 236.9
  TOP w4: R210.2@2039.47,1628.29 2039.47,1610.55 2047.52,1602.5 2077.75,1602.5 2084.75,1609.5 2119.51,1609.5 2127.31,1601.7 2212.85,1601.7 2212.95,1601.8 2230.75,1601.8 U2.G14@2243.76,1614.81
NetR211_2: R211.2 U2.F13 | length 1524.1
  TOP w10: U2.F13@2269.35,1589.22 v1@2287.1,1589.22
  L3-GND/SIG w5: v1(1434.15,1358.68) 1374.01,1358.68 1319.09,1303.76 1254.42,1303.76 1230.71,1327.46 1230.71,1371.26 1244.21,1384.76 1244.21,1436.26 1376.75,1568.8 1987.75,1568.8 2028.55,1609.6 2107.15,1609.6 2133.65,1583.1 2248.46,1583.1 2253.18,1587.82 v1(2288.5,1587.82)
  BOTTOM w4: R211.2@1434.15,1331.73 v1(1434.15,1358.68)
PGOOD: R27.1 R107.2 R138.2 R141.2 R159.1 | length 4455.5
  TOP w15: v1(966.75,2363.5) 1001.55,2328.7 R27.1@1001.55,2304.99
  TOP w20: R107.2@1232.5,680.68 1262.61,680.68 1264.79,678.5 v1(1267.75,678.5) 1267.75,726.9 1403.55,862.7 1403.55,1112.9 1462.25,1171.6 1462.25,1309.1 v1(1462.85,1309.7)
  L3-GND/SIG w20: v1(79.75,747) 184.25,747 201.55,729.7 417.55,729.7 468.35,780.5 796.56,780.5 827.56,749.5 979.29,749.5 1020.29,708.5 1237.75,708.5 v1(1267.75,678.5) ; v1(966.75,2363.5) 1027.16,2423.91 1250.29,2423.91 1256.01,2418.19 1278.55,2418.19 1284.27,2423.91 1372.16,2423.91 1409.3,2461.05 1689.2,2461.05 v1(1788.75,2361.5)
  L4-GND/SIG w20: v1(1462.85,1309.7) 1461.35,1311.2 1461.35,1432.5 1778.05,1749.2 1843.65,1749.2 1923.35,1828.9 1923.35,2000.11 1840.65,2082.81 1840.65,2223.9 1788.75,2275.8 v1(1788.75,2361.5)
  BOTTOM w20: v1(79.75,747) 93.44,733.31 R159.1@127.18,733.31 ; v1(1462.85,1309.7) 1468.55,1315.4 R141.2@1489.16,1315.4 1489.95,1315.4 1489.95,1294 1499.75,1284.2 R138.2@1499.75,1272.4
PMIC_1V2: C3.2 C4.2 C6.2 C7.2 C54.2 C89.2 L1.2 U2.G15 U2.H15 U2.N11 U2.P14 U2.P15 U2.R6 U8.14 | length 1089.9
  TOP w10: 2176.25,1817.5 2199.81,1793.94 U2.P15@2218.17,1793.94 U2.P14@2243.76,1793.94 ; U2.G15@2218.17,1614.81 2169.79,1614.81 v1(2154.75,1629.85) 2165.3,1640.4 U2.H15@2218.17,1640.4
  TOP w12: U2.R6@2448.48,1819.53 2448.48,1848.23 2448.75,1848.5 2448.75,1849.5 2454.75,1855.5 2454.75,1883.95 2466.76,1895.96 C3.2@2466.95,1896.15
  TOP w15: U2.N11@2320.53,1768.35 2320.53,1763.27 v1(2332.7,1751.1)
  TOP w20: v1(2002.75,1888.5) 2002.75,1879.6 2022.45,1859.9 C89.2@2084.85,1859.9 2095.95,1848.8 2137.25,1848.8 2144.95,1848.8 2176.25,1817.5 ; C4.2@2127.02,1629.85 C4.2@2127.41,1629.85 v1(2154.75,1629.85) ; C3.2@2466.95,1896.15 2480.1,1896.15 v1(2491.45,1907.5)
  BOTTOM w10: 1716.55,1314.65 1719.3,1311.9 1728.55,1311.9 1830.45,1311.9 1839.95,1321.4 1870.85,1321.4 1916.65,1367.2 1916.65,1512.6 1858.25,1571
  BOTTOM w20: C7.2@2303.45,1782.5 2303.45,1766.8 2319.15,1751.1 v1(2332.7,1751.1)
  other v1: 1858.45,1673.9 1807.75,1675 1902.75,1690
PMIC_1V8: C30.2 C31.2 C32.2 C40.2 C81.2 L4.2 L6.1 R46.1 R120.2 U5.1 U5.2 U5.4 U5.5 U8.1 | length 390.9
  TOP w4: R46.1@1588.35,1906.7 1628.45,1906.7 v1(1642.1,1920.35)
  BOTTOM w10: 1433.55,1110.5 1491.95,1110.5 1552.8,1171.35 1578.95,1171.35 1590.95,1171.35
  BOTTOM w20: 1644.75,1939 1644.75,2051.1 1670.36,2076.71 R120.2@1670.75,2077.1
  other v1: 1688.85,1807.7 1657.55,1824.4 1646.75,1855.2 1641.35,1886.2
PMIC_2V3: C21.2 C23.2 C25.2 C82.2 L3.2 L5.1 R84.1 U4.7 U4.8 U8.21 | length 718.4
  TOP w20: 1890.65,916.6 1890.65,948.4 1955.97,1013.72 R84.1@1980.42,1013.72 R84.1@1981.2,1013.72
  BOTTOM w10: 1716.55,1171.35 1728.55,1171.35 1772.4,1171.35 1819.15,1124.6 1819.15,1110.8 1845.35,1084.6 1890.35,1084.6 1911.05,1063.9 1911.05,945.81 1852.74,887.5 L3.2@1805.23,887.5 ; v1(2216.25,1032.4) v1@2253.05,1032.4 ; L5.1@2242.55,1064.43 L5.1@2242.55,1062.46 2242.55,1042.9 v1@2253.05,1032.4 ; v1(2253.55,1031.9) v1@2253.05,1032.4
  other v1: 1858.75,812 1900.75,815 1870.75,848 1917.75,852 2152.65,984.4 2189.95,983.9
PMIC_CLK: R97.2 U8.3 | length 1772.1
  TOP w7.08: v1(1418.25,822.7) 1462.85,867.3 1462.85,1005 1453.65,1014.2 1453.65,1111.9 v1(1473.05,1131.3)
  TOP w11: R97.2@387.75,690.55 388.14,690.94 397.75,700.55 v1(397.75,769)
  L3-GND/SIG w9: v1(397.75,769) 397.75,803.5 471.58,877.33 784.92,877.33 880.15,782.1 983.15,782.1 1035.85,729.4 1164.65,729.4 1182.75,747.5 1182.75,757.5 1202.75,777.5 1373.05,777.5 v1(1418.25,822.7)
  BOTTOM w9: v1(1473.05,1131.3) 1489.05,1131.3 1527.75,1170 1527.75,1201.9 1540.05,1214.2 1578.22,1214.2 U8.3@1578.95,1213.47
PMIC_EN1: R102.2 R142.1 U8.7 | length 1317.7
  TOP w4: R102.2@1333,675.77 1333,769.15 1419.65,855.8 1419.65,1105.69 1478.25,1164.29 1478.25,1260.8 1505.65,1288.2 v1(1546.05,1288.2) 1551.35,1293.5 1859.05,1293.5 1907.05,1245.5 1954.75,1245.5 1974.12,1226.13 v1(1989.49,1226.13)
  BOTTOM w4: v1(1546.05,1288.2) 1550.06,1292.21 U8.7@1578.95,1292.21 ; R142.1@1985,1309.54 1985,1230.62 v1(1989.49,1226.13)
PMIC_EN2: R148.1 U8.15 | length 512.7
  L3-GND/SIG w5: v1(1919.75,1337.4) 1920.65,1337.4 1942.9,1315.15 1942.9,1138.85 1926,1121.95 v1(1926,1116)
  BOTTOM w4: U8.15@1728.55,1292.21 1832.96,1292.21 1846.95,1306.2 1888.55,1306.2 v1(1919.75,1337.4) ; v1(1926,1116) 1947.65,1116 1977.36,1145.71 R148.1@1977.75,1146.1
PMIC_EN3: R145.1 U8.2 | length 543.1
  TOP w4: v1(1549.85,1193.79) 1583.05,1226.99 1583.05,1264.5 1603.55,1285 1856.15,1285 1897.85,1243.3 v1(1897.85,1221)
  BOTTOM w4: v1(1549.85,1193.79) U8.2@1578.95,1193.79 ; v1(1897.85,1221) 1897.85,1241.6 1916.43,1260.18 R145.1@1936.19,1260.18
PMIC_NRST: R150.2 U8.20 | length 227.8
  BOTTOM w4: U8.20@1728.55,1193.79 1774.95,1193.79 1807.74,1161 1871.55,1161 1886.8,1145.75 R150.2@1936.49,1145.75
PMICOUT_3V3: C55.2 L2.2 R133.1 R141.1 U8.8 | length 511.4
  BOTTOM w10: U8.8@1583.75,1314.65 1590.95,1314.65
  BOTTOM w15: 1464.69,1386.96 1523.05,1328.6 1523.05,1320.1 1528.14,1315.01 R141.1@1528.5,1314.65 ; R141.1@1528.54,1314.65 1578.95,1314.65 U8.8@1583.75,1314.65
  BOTTOM w20: 1464.69,1386.96 1433.69,1386.96 1418.75,1401.9 1418.75,1493.85 1437.1,1512.2 1438.45,1512.2 1456.75,1530.5 1456.75,1562.69 1471.82,1577.76 L2.2@1500.11,1577.76 ; 1468.85,1664.1 R133.1@1468.85,1698.2 1505.95,1698.2
PMICVIO_3V3: R139.2 R142.2 R143.2 R145.2 R147.2 R148.2 R149.1 R150.1 | length 377
  BOTTOM w20: R147.2@1896.65,1183 R147.2@1897.44,1183 1935.94,1183 R150.1@1936.49,1183.55 ; R143.2@1897.15,1284.3 R143.2@1897.94,1284.3 1915.65,1284.3 1918.15,1286.8 1921.56,1286.8 1943.76,1309 1946.41,1309 1946.66,1309 1946.81,1309.15 R142.2@1947.2,1309.54 ; R139.2@1947.2,1350.04 R142.2@1947.2,1309.54 ; R149.1@2018.89,1183.55 2018.54,1183.9 1977.75,1183.9 1977.4,1183.55 R150.1@1936.49,1183.55 ; R150.1@1936.49,1183.55 R150.1@1936.49,1184.33 1936.49,1220.81 1936.49,1223.45 1936.19,1223.75 1943.5,1223.75 1944.75,1225 1949.75,1225 1965.75,1241 1965.75,1277.5 1947.2,1296.05 R142.2@1947.2,1309.54
RX1: U2.M2 | length 194.8
  TOP w7.08: U2.M2@2550.84,1742.76 2590.93,1742.76 ccw(c2590.93,1859.34) 2660.87,1766.07 ; 2660.9,1766.1 cw(c2700.52,1706.69) 2700.49,1778.1 2738.15,1778.1
RX2: U2.K2 | length 194.9
  TOP w7.08: U2.K2@2550.84,1691.58 2610.71,1691.58 ccw(c2610.71,1772.49) 2657.97,1706.82 ; 2657.99,1706.84 cw(c2682.71,1672.7) 2682.4,1714.85 2699.85,1714.98 cw(c2700.05,1687.18) 2719.71,1706.83 ; 2719.71,1706.82 ccw(c2731.34,1724.27) 2731.34,1703.3 2738.01,1703.3
RX3: U2.H2 | length 194.9
  TOP w7.08: U2.H2@2550.84,1640.4 2610.71,1640.4 cw(c2610.71,1559.49) 2657.97,1625.16 ; 2657.99,1625.14 ccw(c2682.71,1659.28) 2682.4,1617.13 2699.85,1617 ccw(c2700.05,1644.8) 2719.71,1625.15 cw(c2731.34,1607.71) 2731.34,1628.68 2738.01,1628.68
RX4: U2.F2 | length 194.7
  TOP w7.08: U2.F2@2550.84,1589.22 2590.93,1589.22 cw(c2590.93,1472.64) 2660.87,1565.91 ; 2660.9,1565.88 ccw(c2700.52,1625.29) 2700.49,1553.88 2738.15,1553.88
SPICLK1: R75.1 R76.1 U14.8 | length 272
  TOP w4: U14.8@1229.28,1344.01 1229.28,1345.83 1229.28,1371.81 1238.29,1380.82 1274.23,1380.82 1307.06,1347.99 1336.47,1347.99 1344.97,1356.49 R75.1@1346.75,1356.49 1337.49,1365.75 1337.49,1376.24 1342.07,1380.82 1386.62,1380.82 1391.5,1375.94 1391.5,1368.24 R76.1@1379.75,1356.49
SS_CTRL: R119.2 R120.1 U5.8 U5.18 | length 1094
  L4-GND/SIG w5: v1(1635.75,1711.5) 1635.75,1722 1604.45,1753.3 1604.45,1969.21 1637.75,2002.51 1637.75,2095.7 1676.95,2134.9 v1(1676.95,2189.2)
  BOTTOM w4: v1(1635.75,1711.5) 1648.75,1698.5 1724.74,1698.5 1740.75,1714.51 1740.75,1767.01 1757.37,1783.63 U5.18@1757.37,1808.08 ; R120.1@1670.75,2114.9 1671.14,2115.29 1676.95,2121.1 v1(1676.95,2189.2) 1711.15,2189.2 1756.46,2143.89 1759.75,2140.6 1759.75,1967.94 U5.8@1757.37,1965.56
SW0: L2.1 R202.2 U8.10 | length 332.1
  BOTTOM w10: 1615.26,1379.5 1634.06,1360.7 U8.10@1634.06,1303.63
  BOTTOM w14.5: 1552.57,1500.03 1583.6,1469 1583.6,1396.5
  BOTTOM w17: 1583.6,1396.5 1600.6,1379.5 1615.26,1379.5
  BOTTOM w20: R202.2@1494.45,1455.3 R202.2@1494.45,1456.09 1494.45,1483.88 1509.62,1499.05 L2.1@1510.6,1500.03
  BOTTOM w25: L2.1@1510.6,1500.03 1552.57,1500.03
SW1: L1.1 R203.2 U8.12 | length 337.9
  BOTTOM w10: U8.12@1673.43,1303.63 1673.44,1361.74 1693.7,1382
  BOTTOM w14.5: 1724.7,1397.9 1724.7,1469.7 1755.43,1500.43
  BOTTOM w17: 1693.7,1382 1708.8,1382 1724.7,1397.9
  BOTTOM w20: L1.1@1796.8,1500.43 1801.92,1500.43 1816.07,1486.28 1816.07,1457.02 1814.64,1455.59 R203.2@1814.25,1455.2
  BOTTOM w25: 1755.43,1500.43 L1.1@1796.8,1500.43
SW2: L4.1 R204.2 U8.25 | length 359.3
  BOTTOM w10: 1624.3,1093.3 1634.06,1103.06 U8.25@1634.06,1182.37
  BOTTOM w14.5: 1548.67,963.67 1582.6,997.6 1582.6,1068
  BOTTOM w17: 1582.6,1068 1599.6,1085 1616,1085 1624.3,1093.3
  BOTTOM w20: R204.2@1493.45,1010.4 R204.2@1493.45,1009.61 1493.45,974.52 1503.32,964.65 L4.1@1504.3,963.67
  BOTTOM w25: L4.1@1504.3,963.67 1548.67,963.67
SW3: L3.1 R205.2 U8.23 | length 383.8
  BOTTOM w10: U8.23@1673.43,1182.37 1673.44,1106.82 1691.26,1089
  BOTTOM w14.5: 1721.4,1073.2 1721.4,997.2 1753.59,965.01
  BOTTOM w17: 1691.26,1089 1705.6,1089 1721.4,1073.2 ; 1753.59,965.01 1755.43,965.01
  BOTTOM w20: L3.1@1796.3,963.67 1821.32,963.67 1836.55,978.9 1836.55,1013.11 1836.55,1013.8 R205.2@1836.65,1013.9
  BOTTOM w25: 1755.43,965.01 1756.77,963.67 L3.1@1796.3,963.67
TX1: U2.B4 | length 817.7
  TOP w7.08: U2.B4@2499.66,1486.86 2499.66,1082.11 ccw(c2557.07,1082.11) 2557.07,1024.7 2569.35,1024.7 ccw(c2569.35,1082.7) 2627.35,1082.7 2627.35,1159.24 cw(c2666.61,1159.24) 2638.85,1187 cw(c2676.01,1149.87) 2676.01,1202.4 2746.75,1202.4
TX2: U2.B6 | length 815.1
  TOP w7.08: U2.B6@2448.48,1486.86 2448.48,1052.03 ccw(c2597.31,1052.03) 2597.31,903.2 2743.75,903.2
VBUS_1_DETECT: C69.2 R151.1 R153.2 U6.1 | length 147.8
  BOTTOM w7: 266.7,1166.45 U6.1@311.39,1166.45
  BOTTOM w20: R153.2@249.3,1080.24 249.3,1123.54 249.69,1123.93 249.7,1166.06 C69.2@250.09,1166.06 266.31,1166.06 266.7,1166.45
VDDC_1: C62.2 C64.2 C74.2 C75.2 U6.87 U6.115 | length 714.8
  BOTTOM w7: 575.17,1059.68 U6.115@575.17,1107.39 575.17,1148.62 596.35,1169.8 ; 874.57,1308.18 U6.87@917.69,1308.18 964.13,1308.18
  BOTTOM w20: 575.17,1059.68 576.43,1058.42 C75.2@576.43,1039.34 576.43,1038.95 C74.2@619.35,1038.95 ; 596.35,1169.8 601.75,1175.2 601.75,1224.9 685.03,1308.18 874.57,1308.18 ; 964.13,1308.18 980.48,1308.18 992.91,1320.61 993.1,1320.8 992.91,1320.99 992.8,1321.1 C62.2@992.8,1364
VPP_1P7: C8.2 P7.1 U2.L13 | length 3174.2
  TOP w10: U2.L13@2269.35,1717.17 2294.02,1717.17 2296.84,1714.35 v1(2318.74,1714.35)
  L3-GND/SIG w10: 2261.95,1716.3 2316.79,1716.3 v1(2318.74,1714.35)
  L3-GND/SIG w15: P7.1@274.69,2008.65 208.57,1942.53 208.57,1661.59 316.55,1553.61 316.55,1517.92 388.87,1445.6 452.05,1445.6 661.45,1236.2 1153.94,1236.2 1173.84,1256.1 1173.84,1511.71 1291.73,1629.6 1433.35,1629.6 1449.15,1613.8 1935.75,1613.8 1994.45,1672.5 2218.15,1672.5 2261.95,1716.3
  BOTTOM w15: C8.2@2239.75,1715.51 2317.59,1715.5 v1(2318.74,1714.35)
XDSET_1_D_N: J8.2 U6.93 U10.1 | length 2199.2
  TOP w5.2: U10.1@2098.44,529.81 2116.56,529.81 v1(2122.75,536)
  BOTTOM w6: U6.93@917.69,1213.69 920.38,1211 976.31,1211 993.45,1193.86 993.45,1121.69 985.21,1113.45 978.75,1106.99 978.75,787 1007.75,758 1057.25,758 1098.75,799.5 1184.01,799.5 1200.01,783.5 1290.31,783.5 1316.11,757.7 1852.05,757.7 2072.75,537 2121.75,537 v1(2122.75,536) 2115.75,529 2115.75,416 2073.34,373.59 J8.2@2073.34,163.38
XDSET_1_D_P: J8.3 U6.94 U10.4 | length 2198.8
  TOP w5.2: U10.4@2059.07,506.19 2059.06,489.69 v1(2066.75,482)
  BOTTOM w6: U6.94@917.69,1197.94 919.75,1200 971.75,1200 982.45,1189.3 982.45,1126.25 967.75,1111.55 967.75,782.44 1003.19,747 1061.81,747 1103.31,788.5 1179.45,788.5 1195.45,772.5 1285.75,772.5 1311.55,746.7 1847.49,746.7 2066.75,527.44 v1(2066.75,482) 2087.25,502.5 2095.75,502.5 2104.75,493.5 2104.75,420.56 2062.34,378.15 2062.34,210.8 2047.75,196.21 J8.3@2047.75,163.38
XDSET_1_ID: J8.4 R152.2 U10.2 | length 2101
  TOP w4: v1(2018.75,308) 2165.85,455.1 2165.85,547.9 v1(2147.25,566.5) 2108.75,566.5 2082.75,540.5 2082.75,533.81 U10.2@2078.75,529.81
  TOP w10: R152.2@942.99,1210 1035.15,1210 1084.95,1160.2 v1(1084.95,1110.55)
  L3-GND/SIG w10: v1(1084.95,1110.55) 1084.95,1131.2 1098.35,1144.6 1381.85,1144.6 1738.75,787.7 1893.55,787.7 2114.75,566.5 v1(2147.25,566.5)
  BOTTOM w4: v1(2018.75,308) 2022.16,304.59 J8.4@2022.16,163.38
XDSET_1_VBUS: R151.2 R154.2 R161.2 U10.6 | length 2710.2
  TOP w10: U10.6@2098.44,506.19 U10.6@2100.25,506.19
  TOP w15: U10.6@2100.25,506.19 2134.56,506.19 2137.75,503 2137.75,500 v1(2139.75,500)
  TOP w20: v1(157.75,1136) 196.05,1136 213.05,1119 213.05,1028.5 238.85,1002.7 402.65,1002.7 430.95,1031 719.35,1031 800.25,950.1 868.15,950.1 898.75,980.7 R154.2@898.75,1078.81 898.75,1079.6 948.65,1079.6 991.55,1122.5 v1(1017.75,1122.5)
  L3-GND/SIG w15: v1(1017.75,1122.5) 1064.4,1075.85 1088.4,1075.85 1157.75,1006.5 1484.35,1006.5 1721.35,769.5 1877.71,769.5 2031.75,615.46 2031.75,574.06 2105.81,500 v1(2139.75,500)
  BOTTOM w20: v1(157.75,1136) 199.04,1136 211.11,1123.93 R151.2@211.5,1123.54 ; v1(2139.75,500) 2139.25,500 2139.5,499.75 2162.75,476.5 R161.2@2162.75,451.5
XDSET_TCK: R70.2 U6.35 | length 1694.7
  TOP w4: v1(1092.75,1681.5) 1093.75,1682.5 1175.35,1682.5 R70.2@1194.08,1701.23
  L3-GND/SIG w5: v1(384.75,1668) 504.35,1548.4 504.35,1465.5 597.35,1372.5 636.75,1372.5 746.75,1262.5 1114.72,1262.5 1136.35,1284.13 1136.35,1454.64 1111.84,1479.15 1111.84,1496.5 1007.05,1601.29 1007.05,1684.8 1023.96,1701.71 1072.54,1701.71 v1(1092.75,1681.5)
  BOTTOM w4: v1(384.75,1668) 401.94,1685.19 U6.35@401.94,1713.69
XDSET_TDI: R30.2 U6.38 | length 1119.7
  TOP w4: R30.2@1098.5,2279.23 1112.15,2265.58 v1(1112.15,2254.6)
  L4-GND/SIG w5: v1(581.15,2112.1) 665.65,2196.6 1054.15,2196.6 v1(1112.15,2254.6)
  BOTTOM w4: U6.38@449.19,1713.69 449.19,1740.05 442.75,1746.49 442.75,1854.5 422.75,1874.5 422.75,1964.5 472.75,2014.5 488.75,2014.5 508.75,2034.5 508.75,2065.3 555.55,2112.1 v1(581.15,2112.1)
XDSET_TDO: R71.2 U6.37 | length 1869.3
  TOP w4: v1(1116.75,1650.5) 1140.75,1674.5 1200.35,1674.5 R71.2@1227.08,1701.23
  L3-GND/SIG w5: v1(421.75,1769) 444.85,1769 521.15,1692.7 521.15,1465.7 604.35,1382.5 640.95,1382.5 748.05,1275.4 1071.6,1275.4 1084.95,1288.75 1084.95,1297.62 1096.49,1309.16 1112.81,1309.16 1126.35,1322.7 1126.35,1445.26 1101.84,1469.77 1101.84,1487.48 995.55,1593.77 995.55,1688.3 1023.75,1716.5 1100.74,1716.5 1118.75,1698.49 1118.75,1652.5 v1(1116.75,1650.5)
  BOTTOM w4: v1(421.75,1769) 433.44,1757.31 U6.37@433.44,1713.69
XDSET_TMS: R69.2 U6.36 | length 1712.2
  TOP w4: v1(1066.75,1650.5) 1066.75,1690.39 1082.56,1706.2 1157.03,1706.2 R69.2@1162,1701.23
  L3-GND/SIG w5: v1(423.75,1666) 396.65,1693.1 374.35,1693.1 359.65,1678.4 359.65,1647.5 486.25,1520.9 486.25,1467.8 591.55,1362.5 632.55,1362.5 742.55,1252.5 1128.43,1252.5 1151.24,1275.31 1151.24,1566.01 v1(1066.75,1650.5)
  BOTTOM w4: U6.36@417.69,1713.69 417.69,1672.06 v1(423.75,1666)
pads on no net: FID1.1 FID2.1 FID3.1 FID4.1 FID5.1 FID6.1 FID7.1 J1.20 J1.22 J1.32 J1.34 J1.38 J1.40 J1.MH1 J1.MH2 J5.7 J5.20 J6.3 J6.11 J8.7 J8.8 LBL1.0 SW1.1 SW1.3 SW2.1 SW2.3 U1. U5.9 U5.17 U5.21@1730.01,1859.46 U5.21@1730.01,1914.18 U5.21@1784.73,1859.46 U5.21@1784.73,1914.18 U6.2 U6.3 U6.4 U6.5 U6.6 U6.11 U6.12 U6.13 U6.14 U6.15 U6.18 U6.19 U6.20 U6.21 U6.22 U6.23 U6.24 U6.27 U6.29 U6.30 U6.31 U6.32 U6.41 U6.42 U6.43 U6.44 U6.45 U6.46 U6.49 U6.50 U6.53 U6.54 U6.56 U6.57 U6.65 U6.67 U6.71 U6.72 U6.73 U6.74 U6.75 U6.76 U6.77 U6.78 U6.81 U6.82 U6.83 U6.84 U6.85 U6.86 U6.91 U6.92 U6.97 U6.98 U6.99 U6.100 U6.102 U6.103 U6.104 U6.105 U6.106 U6.107 U6.108 U6.109 U6.110 U6.111 U6.112 U6.116 U6.117 U6.118 U6.119 U6.120 U6.121 U6.123 U6.124 U6.125 U6.126 U6.127 U6.128 U7.3 U8. U9.7 U11.7 U14.9 U14.12

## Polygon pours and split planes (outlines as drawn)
no net on Top Solder (solid): 1698.75,2487 1698.75,2382 2076.75,2382 2076.75,2309 2460.75,2309 2460.75,2487 1698.75,2487
no net on Top Solder (solid): 87 vertices, not listed, extent 2360.75,777.5 3282.75,1912.5
no net on Top Solder (solid): 2060.78,2172.88 2112.88,2172.88 2112.88,2196.48 2060.78,2196.48 2060.78,2172.88
no net on Top Solder (solid): 2060.78,2122.88 2112.88,2122.88 2112.88,2146.48 2060.78,2146.48 2060.78,2122.88
no net on Top Solder (solid): 2060.78,2072.88 2112.88,2072.88 2112.88,2096.48 2060.78,2096.48 2060.78,2072.88
no net on Top Solder (solid): 1842.88,2172.88 1894.98,2172.88 1894.98,2196.48 1842.88,2196.48 1842.88,2172.88
no net on Top Solder (solid): 1842.88,2122.88 1894.98,2122.88 1894.98,2146.48 1842.88,2146.48 1842.88,2122.88
no net on Top Solder (solid): 1842.88,2022.88 1894.98,2022.88 1894.98,2046.48 1842.88,2046.48 1842.88,2022.88
no net on Top Solder (solid): 2060.78,2022.88 2112.88,2022.88 2112.88,2046.48 2060.78,2046.48 2060.78,2022.88
no net on Top Solder (solid): 1842.88,2072.88 1894.98,2072.88 1894.98,2096.48 1842.88,2096.48 1842.88,2072.88
no net on Bottom Solder (solid): 72 vertices, not listed, extent 2093.75,17.5 3284.85,1693.5
GND on TOP "TOP-GND 1" (solid, remove dead copper, pour order 1007): 2460.75,2487 2460.75,2309 2076.75,2309 2076.75,2382 1698.75,2382 1698.75,2487 2460.75,2487
no net on TOP "Top Layer-No Net" (solid, pour order 956): 2211.13,2344.45 2211.13,2350.35 2222.94,2350.35 2246.56,2350.94 2394.35,2350.94 2417.97,2350.35 2429.78,2350.35 2429.78,2344.45 2417.97,2344.45 2394.35,2343.86 2246.56,2343.86 2222.94,2344.45
no net on TOP "Top Layer-No Net" (solid, pour order 951): 1734.28,2432.55 1746.09,2432.55 1769.71,2431.96 2395.15,2431.96 2418.77,2432.55 2430.58,2432.55 2430.58,2438.45 2418.77,2438.45 2395.15,2439.04 1769.71,2439.04 1746.09,2438.45 1734.28,2438.45
RX4 on TOP "TOP-RX4" (solid, pour order 948): 38 vertices, not listed, extent 2736.95,1524.17 3184.98,1583.23
RX3 on TOP "TOP-RX3" (solid, pour order 949): 38 vertices, not listed, extent 2736.95,1598.97 3184.98,1658.03
RX2 on TOP "TOP-RX2" (solid, pour order 950): 38 vertices, not listed, extent 2736.95,1673.77 3184.98,1732.83
RX1 on TOP "TOP-RX1" (solid, pour order 952): 38 vertices, not listed, extent 2736.95,1748.57 3184.98,1807.63
GND on TOP "TOP-GND 4" (solid, pour order 978): 38 vertices, not listed, extent 2736.95,1449.37 3184.98,1508.43
GND on TOP "TOP-GND 5" (solid, pour order 981): 38 vertices, not listed, extent 2736.95,1823.37 3184.98,1882.43
PMIC_1V2 on TOP "TOP-PMIC_1V2" (solid, pour order 979): 40 vertices, not listed, extent 1988.35,1837.9 2151.05,1900.5
TX2 on TOP "TOP-TX2" (solid, remove dead copper, pour order 1043): 38 vertices, not listed, extent 2736.95,873.67 3184.98,932.73
TX1 on TOP "TOP-TX1" (solid, pour order 1042): 38 vertices, not listed, extent 2736.95,1172.87 3184.98,1231.93
NetC26_1 on TOP "TOP-UNNAMED_39_CAPPOLARIZED_I74_1" (solid, pour order 953): 340 vertices, not listed, extent 1471.05,182.8 1838.25,913.5
NetC85_2 on TOP "TOP-UNNAMED_7_CAPNONPOLARIZED_I5_2" (solid, pour order 954): 194 vertices, not listed, extent 384.65,1079 496.19,1218
PMIC_2V3 on TOP "TOP-PMIC_2V3" (solid, pour order 957): 258 vertices, not listed, extent 1843.65,791.5 2266.05,1059.2
MCU_5V on TOP "TOP-MCU_5V" (solid, pour order 962): 124 vertices, not listed, extent 521.77,668 690.75,772
NetF1_2 on TOP "TOP-UNNAMED_39_FUSE_I161_1" (solid, pour order 965): 146 vertices, not listed, extent 1188.75,269 1438.25,500
NetJ1_1 on TOP "TOP-UNNAMED_43_QSH03001XD_I1_1" (solid, pour order 966): 466 vertices, not listed, extent 1177.39,1891 1453.7,2296
NetR40_1 on TOP "TOP-UNNAMED_41_RESISTOR_I120_1" (solid, pour order 967): 2112.88,2146.48 2060.78,2146.48 2060.78,2122.88 2112.88,2122.88 2112.88,2146.48
NetR39_2 on TOP "TOP-UNNAMED_41_RESISTOR_I119_2" (solid, pour order 968): 1894.98,2146.48 1842.88,2146.48 1842.88,2122.88 1894.98,2122.88 1894.98,2146.48
NetR45_1 on TOP "TOP-UNNAMED_41_RESISTOR_I118_1" (solid, pour order 969): 2112.88,2046.48 2060.78,2046.48 2060.78,2022.88 2112.88,2022.88 2112.88,2046.48
NetR44_1 on TOP "TOP-UNNAMED_41_RESISTOR_I117_1" (solid, pour order 970): 2112.88,2096.48 2060.78,2096.48 2060.78,2072.88 2112.88,2072.88 2112.88,2096.48
NetR42_2 on TOP "TOP-UNNAMED_41_RESISTOR_I116_2" (solid, pour order 971): 1894.98,2096.48 1842.88,2096.48 1842.88,2072.88 1894.98,2072.88 1894.98,2096.48
PMIC_1V8 on TOP "TOP-PMIC_1V8" (solid, pour order 972): 210 vertices, not listed, extent 1584.35,1792.5 1702.75,2024.9
AR_VOUT_PA on TOP "TOP-AR_VOUT_PA" (solid, pour order 975): 190 vertices, not listed, extent 2536.75,1315 2648.75,1493.98
AR_QSPI_CS on TOP "TOP-AR_QSPI_CS" (solid, pour order 977): 1894.98,2196.48 1842.88,2196.48 1842.88,2172.88 1894.98,2172.88 1894.98,2196.48
PMIC_1V2 on TOP "TOP-PMIC_1V2 1" (solid, pour order 980): 198 vertices, not listed, extent 2449.77,1853.5 2499.73,1918.5
PMIC_1V2 on TOP "TOP-PMIC_1V2 2" (solid, pour order 982): 96 vertices, not listed, extent 2121.75,1611.72 2223.75,1643.18
AR_1V8 on TOP "TOP-AR_1V8" (solid, pour order 985): 271 vertices, not listed, extent 2126.75,1077.5 2272.75,1307.5
AR_1P3_RF2 on TOP "TOP-AR_1P3_RF2" (solid, pour order 989): 213 vertices, not listed, extent 1679.85,1912.5 1887.75,2027.5
AR_1P3_RF1 on TOP "TOP-AR_1P3_RF1" (solid, pour order 991): 98 vertices, not listed, extent 1812.75,1782.5 1887.75,1877.5
5V_IN on TOP "TOP-5V_IN" (solid, pour order 993): 140 vertices, not listed, extent 439.65,1204 503.85,1307
5V_IN on TOP "TOP-5V_IN 1" (solid, pour order 994): 178 vertices, not listed, extent 1601.75,2177.75 1764.75,2365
